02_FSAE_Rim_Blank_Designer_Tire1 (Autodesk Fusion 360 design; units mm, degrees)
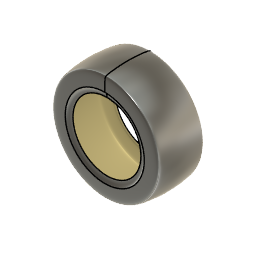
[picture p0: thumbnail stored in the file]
part number: 2026-07-27-09-56-27-671
sketch "Sketch1" plane through (0, 0, 0) normal (1, 0, 0) x axis (0, 1, 0)
  line L1 (153.5, 0) -> (0, 0)
  line L2 (0, 119.5) -> (0, 104)
  line L3 (143.5, 124.5) -> (5, 124.5)
  line L4 (148.5, 134.75) -> (148.5, 129.5)
  line L5 (153.5, 138.25) -> (152, 138.25)
  line L6 (2.5, 119.5) -> (2.5, 104)
  line L7 (143.5, 122) -> (5, 122)
  line L8 (151, 134.75) -> (151, 129.5)
  line L9 (153.5, 135.75) -> (152, 135.75)
  line L10 (2.5, 104) -> (0, 104)
  line L11 (153.5, 135.75) -> (153.5, 138.25)
  arc A1 centre (152, 134.75) radius 3.5 clockwise from (148.5, 134.75) to (152, 138.25)
  arc A2 centre (143.5, 129.5) radius 5 clockwise from (148.5, 129.5) to (143.5, 124.5)
  arc A3 centre (5, 119.5) radius 5 clockwise from (0, 119.5) to (5, 124.5)
  arc A4 centre (5, 119.5) radius 2.5 clockwise from (2.5, 119.5) to (5, 122)
  arc A5 centre (143.5, 129.5) radius 7.5 clockwise from (151, 129.5) to (143.5, 122)
  arc A6 centre (152, 134.75) radius 1 clockwise from (151, 134.75) to (152, 135.75)
  point P1 (0, 0)
  point P2 (0, 0)
  point P4 (0, 104)
  point P3 (153.5, 0)
  point P7 (153.5, 138.25)
  point P6 (148.5, 124.5)
  point P5 (0, 124.5)
  coincident P1 P2
  horizontal L1
  perpendicular L1 L2
  perpendicular L2 L3
  perpendicular L3 L4
  perpendicular L4 L5
  vertical P1 P4
  vertical P3 P7
  tangent L4 A1
  tangent L5 A1
  coincident P6 L3
  coincident P6 L4
  tangent L3 A2
  tangent L4 A2
  coincident P5 L2
  coincident P5 L3
  tangent L2 A3
  tangent L3 A3
  equal A2 A3
  perpendicular L6 L10
  perpendicular L9 L11
  dimension "d1" distance P2 P3 = 153.5
  dimension "d2" = 208
  dimension "d3" = 249
  dimension "d4" = 276.5
  dimension "d5" distance P5 P6 = 148.5
  dimension "d6" radius A1 = 3.5
  dimension "d7" radius A2 = 5
  dimension "d8" = 2.5
revolve "Revolve1" sketch "Sketch1" AlongAngle 360 bodies "FSAE Rim Back"
sketch "Sketch2" plane through (0, 0, 0) normal (0, -1, 0) x axis (1, 0, 0)
  circle C1 centre (0, 0) radius 104
  circle C2 centre (0, 0) radius 119.5
  circle C3 centre (0, 0) radius 112
  circle C4 centre (0, 112) radius 2.15
  point P1 (0, 0)
  point P3 (0, 0)
  point P4 (0, 112)
  coincident P1 P3
  coincident C3 P4
  vertical P3 P4
  dimension "d10" diameter C3 = 224
  dimension "d11" diameter C4 = 4.3
extrude "Extrude1" cut sketch "Sketch2" profile of C4 to an object
circular_pattern "C-Pattern1" TotalAngle 360
canvas "Canvas1"
move "Move1"
sketch "Sketch4" plane through (0, 0, 0) normal (1, 0, 0) x axis (0, 1, 0)
  line L1 (14, 0) -> (0, 0)
  line L2 (14, 72.5) -> (14, 0)
  line L3 (-8, 102.5) -> (14, 72.5)
  line L4 (-8, 124.5) -> (-8, 102.5)
  line L5 (-23.5, 124.5) -> (-8, 124.5)
  line L6 (-23.5, 138) -> (-23.5, 124.5)
  line L7 (-28.25, 138) -> (-23.5, 138)
  line L8 (-28.25, 0) -> (-28.25, 138)
  line L9 (0, 0) -> (-28.25, 0)
  line L10 (-13, 118.1658) -> (-28.25, 119.5)
  line L11 (-13, 102.5) -> (-13, 118.1658)
  line L12 (0, 68.6338) -> (-13, 102.5)
  line L13 (0, 0) -> (0, 68.6338)
  point P1 (0, 0)
  point P2 (0, 0)
  point P11 (0, 0)
  point P12 (-28.25, 119.5)
  point P5 (-8, 102.5)
  point P14 (-13, 102.5)
  point P3 (14, 0)
  point P4 (14, 72.5)
  point P6 (-8, 124.5)
  point P8 (-23.5, 138)
  point P9 (-28.25, 138)
  coincident P1 P2
  horizontal L1
  perpendicular L1 L2
  perpendicular L1 L4
  perpendicular L4 L5
  perpendicular L5 L6
  perpendicular L6 L7
  coincident P1 P11
  collinear L1 L9
  perpendicular L8 L9
  coincident L8 P12
  parallel L8 L11
  vertical L13
  horizontal P5 P14
  dimension "d29" distance P2 P3 = 14
  dimension "d30" = 145
  dimension "d31" = 205
  dimension "d32" = 249
  dimension "d33" = 276
  dimension "d34" distance P4 P6 = 22
  dimension "d35" distance P6 P8 = 15.5
  dimension "d36" distance P8 P9 = 4.75
  dimension "d37" distance L4 L11 = 5
  dimension "d38" angle L12 L13 = 159
  dimension "d39" angle L10 L11 = 95
  dimension "d40" = 239
revolve "Revolve3" sketch "Sketch4" AlongAngle 360 bodies "FSAE Rim Front"
sketch "Sketch5" plane through (0, 0, 0) normal (0, -1, 0) x axis (1, 0, 0)
  circle C1 centre (0, 0) radius 68.6338
  circle C2 centre (0, 0) radius 33
  point P1 (0, 0)
  point P3 (0, 0)
  coincident P1 P3
  dimension "d42" diameter C2 = 66
extrude "Extrude2" cut sketch "Sketch5" profile of C2 to an object
sketch "Sketch6" plane through (0, 0, 0) normal (0, -1, 0) x axis (1, 0, 0)
  circle C1 centre (0, 0) radius 33
  circle C2 centre (0, 0) radius 68.6338
  circle C3 centre (0, 0) radius 50.8
  point P1 (0, 0)
  point P4 (0, 0)
  point P3 (0, 50.8)
  coincident P1 P4
  coincident P3 C3
  vertical P1 P3
  dimension "d45" diameter C3 = 101.6
hole "Hole1" HoleDiameter 10.5 TipAngle 180 CBDepth 5 CBDiameter 20
chamfer "Chamfer2" sketch "Sketch1" distance 0.5
circular_pattern "C-Pattern2" TotalAngle 360
sketch "Sketch7" plane through (0, -13, 0) normal (0, -1, 0) x axis (1, 0, 0)
  circle C1 centre (0, 0) radius 102.5
  circle C2 centre (0, 0) radius 118.1658
  circle C3 centre (0, 0) radius 112
  point P1 (0, 0)
  point P3 (0, 0)
  point P4 (0, 112)
  coincident P1 P3
  coincident C3 P4
  vertical P1 P4
  dimension "d53" diameter C3 = 224
hole "Hole2" HoleDiameter 4.3 TipAngle 180
circular_pattern "C-Pattern3" TotalAngle 360
fillet "Fillet1" radius 1 3 2
chamfer "Chamfer1" distance 0.5
form "Form1"
named bodies: "FSAE Rim Back", "FSAE Rim Front"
